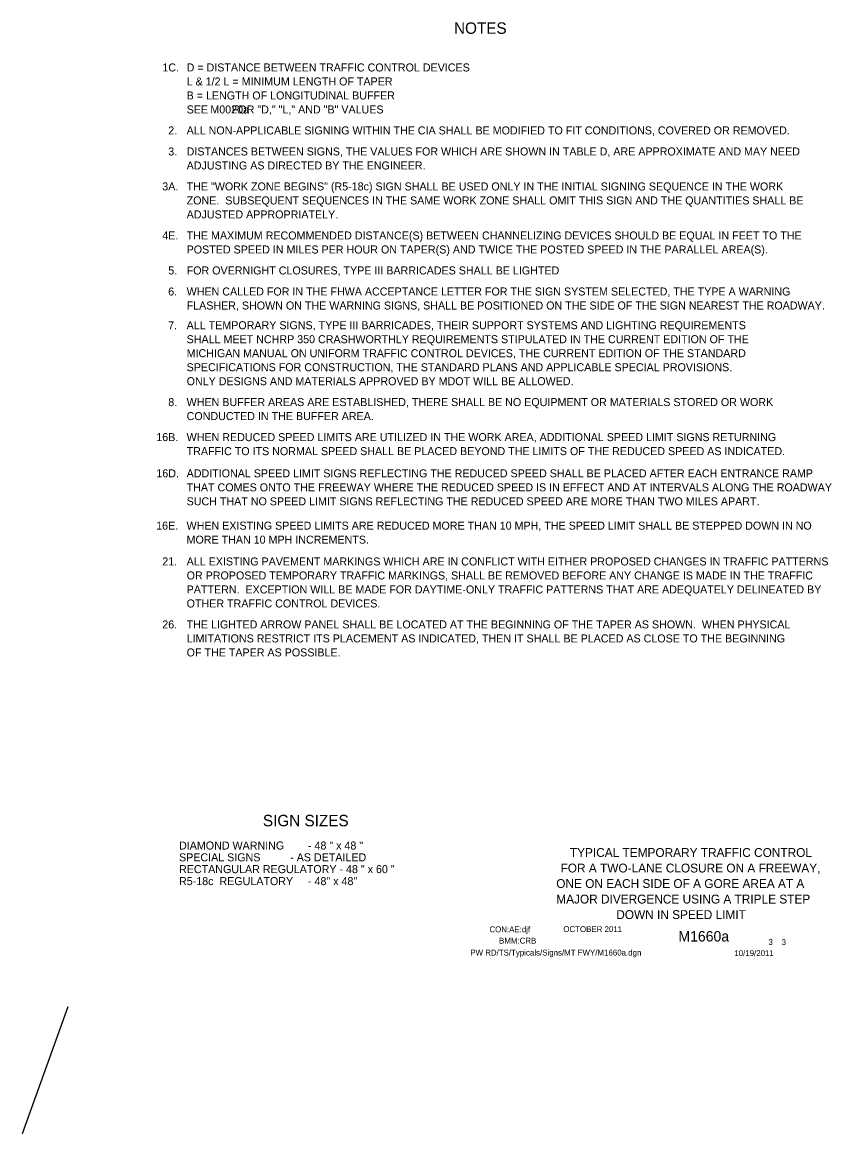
# Model space of a CAD drawing. Extents: x 16519 to 19508, y 5743 to 6974.
# Drawn here: x 18658 to 19508, y 5747 to 6913 of the extents above; entities that cross this region are included whole.
import ezdxf

# ---------------------------------------------------------------- set-up
doc = ezdxf.new("R2010")
doc.units = 0
for name, color, linetype in [('BORDER', 7, 'Continuous'), ('BORDER_SIGNAL_WO', 7, 'Continuous'), ('TYPICAL_TEXT_DIMEN_PR', 7, 'Continuous')]:
    doc.layers.add(name, color=color, linetype=linetype)

msp = doc.modelspace()

# ---------------------------------------------------------------- linework, layer by layer
at = {"layer": 'TYPICAL_TEXT_DIMEN_PR'}
msp.add_line((18705.8, 5880), (18658, 5746.6), dxfattribs=at)

# ---------------------------------------------------------------- texts
at = {"layer": 'BORDER'}
for s, p in [('TYPICAL TEMPORARY TRAFFIC CONTROL', (19233.2, 6037.2)), ('FOR A TWO-LANE CLOSURE ON A FREEWAY,', (19223.4, 6020.9)), ('ONE ON EACH SIDE OF A GORE AREA AT A ', (19218.9, 6004.6)), ('MAJOR DIVERGENCE USING A TRIPLE STEP ', (19218.9, 5988.3)), ('DOWN IN SPEED LIMIT', (19281.9, 5972))]:
    msp.add_text(s, height=9.3, dxfattribs=at).set_placement(p)
at = {"layer": 'BORDER_SIGNAL_WO'}
for s, height, p in [('CON:AE:djf  ', 6.2, (19148.7, 5958.1)), ('    OCTOBER 2011    ', 6.2, (19217.1, 5958.3)), ('BMM:CRB   ', 6.2, (19158.8, 5946.2)), ('    M1660a   ', 11, (19330.9, 5948.4)), ('PW RD/TS/Typicals/Signs/MT FWY/M1660a.dgn      ', 6.2, (19128.6, 5933.7)), ('10/19/2011    ', 6.2, (19405.9, 5933.1)), (' 3    3 ', 6.2, (19439.4, 5944.7))]:
    msp.add_text(s, height=height, dxfattribs=at).set_placement(p)
at = {"layer": 'TYPICAL_TEXT_DIMEN_PR'}
for s, height, p in [('NOTES', 12, (19111.5, 6901.3)), ('1C.', 8.4, (18805.2, 6861.8)), ('D = DISTANCE BETWEEN TRAFFIC CONTROL DEVICES', 8.4, (18830.7, 6861.8)), ('L & 1/2 L = MINIMUM LENGTH OF TAPER', 8.4, (18830.7, 6847.1)), ('B = LENGTH OF LONGITUDINAL BUFFER', 8.4, (18830.7, 6832.4)), ('SEE        FOR "D," "L," AND "B" VALUES', 8.4, (18830.7, 6817.7)), ('M0020a', 8.4, (18855.6, 6817.7)), ('2.', 8.4, (18811.4, 6795.7)), ('ALL NON-APPLICABLE SIGNING WITHIN THE CIA SHALL BE MODIFIED TO FIT CONDITIONS, COVERED OR REMOVED.', 8.4, (18830.7, 6795.7)), ('3.', 8.4, (18811.4, 6773.6)), ('DISTANCES BETWEEN SIGNS, THE VALUES FOR WHICH ARE SHOWN IN TABLE D, ARE APPROXIMATE AND MAY NEED', 8.4, (18830.7, 6773.6)), ('ADJUSTING AS DIRECTED BY THE ENGINEER.', 8.4, (18830.7, 6758.9)), ('3A.', 8.4, (18805.1, 6736.9)), ('THE "WORK ZONE BEGINS" (R5-18c) SIGN SHALL BE USED ONLY IN THE INITIAL SIGNING SEQUENCE IN THE WORK', 8.4, (18830.7, 6736.9)), ('ZONE.  SUBSEQUENT SEQUENCES IN THE SAME WORK ZONE SHALL OMIT THIS SIGN AND THE QUANTITIES SHALL BE', 8.4, (18830.7, 6722.2)), ('ADJUSTED APPROPRIATELY.', 8.4, (18830.7, 6707.5)), ('4E.', 8.4, (18805.1, 6685.4)), ('THE MAXIMUM RECOMMENDED DISTANCE(S) BETWEEN CHANNELIZING DEVICES SHOULD BE EQUAL IN FEET TO THE', 8.4, (18830.7, 6685.4)), ('POSTED SPEED IN MILES PER HOUR ON TAPER(S) AND TWICE THE POSTED SPEED IN THE PARALLEL AREA(S).', 8.4, (18830.7, 6670.7)), ('5.', 8.4, (18811.4, 6648.7)), ('FOR OVERNIGHT CLOSURES, TYPE III BARRICADES SHALL BE LIGHTED', 8.4, (18830.7, 6648.7)), ('6.', 8.4, (18811.3, 6626.6)), ('WHEN CALLED FOR IN THE FHWA ACCEPTANCE LETTER FOR THE SIGN SYSTEM SELECTED, THE TYPE A WARNING ', 8.4, (18830.7, 6626.6)), ('FLASHER, SHOWN ON THE WARNING SIGNS, SHALL BE POSITIONED ON THE SIDE OF THE SIGN NEAREST THE ROADWAY.', 8.4, (18830.7, 6611.9)), ('7.', 8.4, (18811.3, 6591.1)), ('ALL TEMPORARY SIGNS, TYPE III BARRICADES, THEIR SUPPORT SYSTEMS AND LIGHTING REQUIREMENTS', 8.4, (18830.7, 6591.2)), ('SHALL MEET NCHRP 350 CRASHWORTHLY REQUIREMENTS STIPULATED IN THE CURRENT EDITION OF THE', 8.4, (18830.7, 6576.5)), ('MICHIGAN MANUAL ON UNIFORM TRAFFIC CONTROL DEVICES, THE CURRENT EDITION OF THE STANDARD', 8.4, (18830.7, 6561.8)), ('SPECIFICATIONS FOR CONSTRUCTION, THE STANDARD PLANS AND APPLICABLE SPECIAL PROVISIONS.', 8.4, (18830.7, 6547.1)), ('ONLY DESIGNS AND MATERIALS APPROVED BY MDOT WILL BE ALLOWED.', 8.4, (18830.7, 6532.4)), ('8.', 8.4, (18811.4, 6510.5)), ('WHEN BUFFER AREAS ARE ESTABLISHED, THERE SHALL BE NO EQUIPMENT OR MATERIALS STORED OR WORK     ', 8.4, (18830.7, 6510.5)), ('CONDUCTED IN THE BUFFER AREA.', 8.4, (18830.7, 6495.8)), ('16B.', 8.4, (18798.8, 6473.7)), ('WHEN REDUCED SPEED LIMITS ARE UTILIZED IN THE WORK AREA, ADDITIONAL SPEED LIMIT SIGNS RETURNING', 8.4, (18830.7, 6473.7)), ('TRAFFIC TO ITS NORMAL SPEED SHALL BE PLACED BEYOND THE LIMITS OF THE REDUCED SPEED AS INDICATED.', 8.4, (18830.7, 6459)), ('16D.', 8.4, (18798.9, 6435.7)), ('ADDITIONAL SPEED LIMIT SIGNS REFLECTING THE REDUCED SPEED SHALL BE PLACED AFTER EACH ENTRANCE RAMP', 8.4, (18830.7, 6435.7)), ('THAT COMES ONTO THE FREEWAY WHERE THE REDUCED SPEED IS IN EFFECT AND AT INTERVALS ALONG THE ROADWAY', 8.4, (18830.7, 6421)), ('SUCH THAT NO SPEED LIMIT SIGNS REFLECTING THE REDUCED SPEED ARE MORE THAN TWO MILES APART.', 8.4, (18830.7, 6406.3)), ('16E.', 8.4, (18798.7, 6380.8)), ('WHEN EXISTING SPEED LIMITS ARE REDUCED MORE THAN 10 MPH, THE SPEED LIMIT SHALL BE STEPPED DOWN IN NO', 8.4, (18830.6, 6380.8)), ('MORE THAN 10 MPH INCREMENTS.', 8.4, (18830.6, 6366.1)), ('21.', 8.4, (18805.1, 6343.2)), ('ALL EXISTING PAVEMENT MARKINGS WHICH ARE IN CONFLICT WITH EITHER PROPOSED CHANGES IN TRAFFIC PATTERNS', 8.4, (18830.7, 6343.2)), ('OR PROPOSED TEMPORARY TRAFFIC MARKINGS, SHALL BE REMOVED BEFORE ANY CHANGE IS MADE IN THE TRAFFIC', 8.4, (18830.7, 6328.5)), ('PATTERN.  EXCEPTION WILL BE MADE FOR DAYTIME-ONLY TRAFFIC PATTERNS THAT ARE ADEQUATELY DELINEATED BY', 8.4, (18830.7, 6313.8)), ('OTHER TRAFFIC CONTROL DEVICES.', 8.4, (18830.7, 6299.1)), ('26.', 8.4, (18805.1, 6277.1)), ('THE LIGHTED ARROW PANEL SHALL BE LOCATED AT THE BEGINNING OF THE TAPER AS SHOWN.  WHEN PHYSICAL', 8.4, (18830.7, 6277.1)), ('LIMITATIONS RESTRICT ITS PLACEMENT AS INDICATED, THEN IT SHALL BE PLACED AS CLOSE TO THE BEGINNING', 8.4, (18830.7, 6262.4)), ('OF THE TAPER AS POSSIBLE.', 8.4, (18830.7, 6247.7)), ('SIGN SIZES', 12, (18910.8, 6069.4)), ('DIAMOND WARNING        - 48 " x 48 "', 8.4, (18822.7, 6045)), ('SPECIAL SIGNS          - AS DETAILED', 8.4, (18822.7, 6032.6)), ('RECTANGULAR REGULATORY - 48 " x 60 "', 8.4, (18822.7, 6020.2)), ('R5-18c  REGULATORY     - 48" x 48"', 8.4, (18822.7, 6007.6))]:
    msp.add_text(s, height=height, dxfattribs=at).set_placement(p)

doc.saveas('drawing.dxf')
